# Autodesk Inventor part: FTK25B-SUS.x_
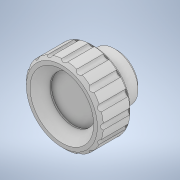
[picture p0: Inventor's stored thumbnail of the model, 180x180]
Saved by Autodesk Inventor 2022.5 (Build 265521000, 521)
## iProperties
Created: 2023-10
Part Number: FTK25B-SUS.x_
Material: 一般
Document SubType Name: Modeling
Designer: ImaoCorp
Density: 1 g/cm^3
Appearance: 既定
Sending System: SOLIDWORKS 2021-2021301
MC: AMD64
MC_MODEL: Intel64 Family 6 Model 60 Stepping 3, GenuineIntel
OS: Windows_NT
FRU: Parasolid Version 32.1, build 255,  1- 1-2021
FORMAT: text
GUISE: transmit
KEY: FTK25B-SUS
FILE: FTK25B-SUS.x_t
DATE: Tue Oct 17 11:07:45 2023
Author: ImaoCorp
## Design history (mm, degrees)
feature "Base1"
node "ソリッド1"
